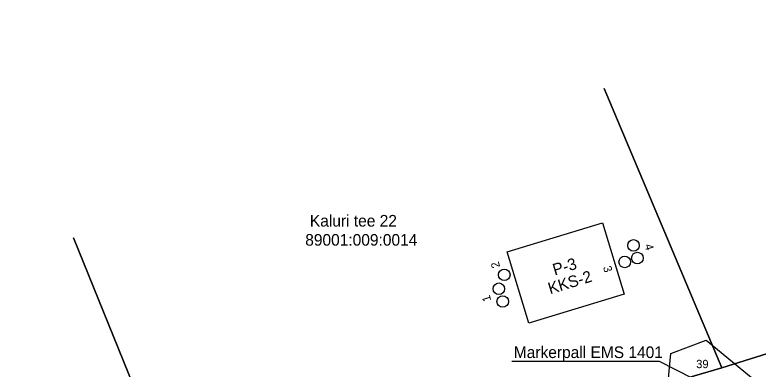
# Model space of a CAD drawing. Extents: x 546339 to 546593, y 6597108 to 6597251.
# Drawn here: x 546389.31 to 546434.18, y 6597180.99 to 6597202.36 of the extents above; entities that cross this region are included whole.
import ezdxf

# ---------------------------------------------------------------- set-up
doc = ezdxf.new("R2010")
doc.units = 0
for name, color, linetype in [('ABIJOONIS', 7, 'Continuous'), ('KOORDPUNKT', 7, 'Continuous'), ('MOOTPIIR', 7, 'Continuous'), ('PIIR', 7, 'Continuous'), ('SITRASS', 7, 'Continuous')]:
    doc.layers.add(name, color=color, linetype=linetype)

msp = doc.modelspace()

# ---------------------------------------------------------------- linework, layer by layer
at = {"layer": 'ABIJOONIS'}
msp.add_lwpolyline([(546426.085, 6597185.51), (546420.344, 6597183.765), (546419.035, 6597188.07), (546424.776, 6597189.815)], close=True, dxfattribs=at)
for centre in [(546426.654, 6597188.452), (546426.121, 6597187.454), (546426.886, 6597187.687), (546418.854, 6597186.679), (546418.525, 6597185.835), (546418.757, 6597185.07)]:
    msp.add_circle(centre, 0.35, dxfattribs=at)
at = {"layer": 'MOOTPIIR'}
msp.add_lwpolyline([(546443.888, 6597176.348), (546374.62, 6597155.63), (546372.739, 6597147.606), (546361.644, 6597146.697), (546361.895, 6597151.274), (546368.79, 6597152.088), (546371.486, 6597159.799), (546428.467, 6597177.226), (546428.906, 6597181.927), (546431.038, 6597182.742), (546435.363, 6597179.169)], dxfattribs=at)
at = {"layer": 'PIIR'}
for points in [[(546424.887, 6597197.926), (546431.99, 6597181.07), (546466.79, 6597191.98), (546459.55, 6597209.598)], [(546510.07, 6597205.36), (546491.04, 6597199.45), (546466.79, 6597191.98), (546431.99, 6597181.07), (546399.93, 6597171.7), (546399.49, 6597172.55), (546362.07, 6597160.42), (546350.54, 6597167.22), (546341.457, 6597167.537)], [(546392.84, 6597188.911), (546399.49, 6597172.55), (546399.93, 6597171.7), (546431.99, 6597181.07), (546424.887, 6597197.926)], [(546356.198, 6597174.862), (546362.07, 6597160.42), (546399.49, 6597172.55), (546392.84, 6597188.911)]]:
    msp.add_lwpolyline(points, dxfattribs=at)
at = {"layer": 'SITRASS'}
msp.add_lwpolyline([(546419.308, 6597181.465), (546428.205, 6597181.465), (546430.224, 6597180.437)], dxfattribs=at)

# ---------------------------------------------------------------- texts
at = {"layer": 'ABIJOONIS'}
for s, height, rotation, p in [('4', 0.5, 286.9069, (546427.313, 6597188.463)), ('P-3', 0.7, 16.9069, (546421.897, 6597186.632)), ('2', 0.5, 106.9069, (546418.611, 6597187.166)), ('3', 0.5, 286.9069, (546424.808, 6597187.136)), ('KKS-2', 0.7, 16.9069, (546421.619, 6597185.502)), ('1', 0.5, 106.9069, (546418.072, 6597185.142))]:
    msp.add_text(s, height=height, rotation=rotation, dxfattribs=at).set_placement(p)
at = {"layer": 'KOORDPUNKT'}
msp.add_text('39', height=0.5, dxfattribs=at).set_placement((546430.439, 6597181.05))
at = {"layer": 'PIIR'}
for s, p in [('Kaluri tee 22', (546407.118, 6597189.59)), ('89001:009:0014', (546406.838, 6597188.437))]:
    msp.add_text(s, height=0.7, dxfattribs=at).set_placement(p)
at = {"layer": 'SITRASS'}
msp.add_text('Markerpall EMS 1401', height=0.7, dxfattribs=at).set_placement((546419.429, 6597181.658))

doc.saveas('drawing.dxf')
